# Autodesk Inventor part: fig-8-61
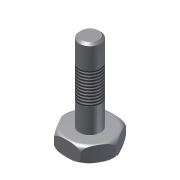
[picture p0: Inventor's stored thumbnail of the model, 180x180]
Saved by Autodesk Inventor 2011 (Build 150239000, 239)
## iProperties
Shininess: 77.0
Length Units: 11269
Angle Units: 11279
Time Units: 11290
Mass Units: 11283
Length Display Precision: 3
Angle Display Precision: 2
Created: 2002-01
Part Number: fig-8-61
Document SubType Name: Modeling
Designer: ***
Density: 1 g/cm^3
Density: 0.0
Volumn: 0.0
Area: 0.0
PropertySet Name: Model Information
Control State: 0
Master: False
Checked Out: False
Author: ***
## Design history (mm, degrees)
sketch "Sketch1"
  geometry: C1 r 25 at (0, 0)
  constraints: 1 centre point
  dimensions: "d0" = 50 diameter of C1
extrude "Extrusion1" new body sketch "Sketch1" distance "d1" = 15; taper "d2" = 0 deg
fillet "Fillet1" dims "d3" = 5
sketch "Sketch2"
  geometry: L1 (25.058, 0)-(12.529, -21.701); L2 (12.529, -21.701)-(-12.529, -21.701); L3 (-12.529, -21.701)-(-25.058, 0); L4 (-25.058, 0)-(-12.529, 21.701); L5 (-12.529, 21.701)-(12.529, 21.701); L6 (12.529, 21.701)-(25.058, 0); 1 further point
  constraints: 12 end point, 11 other
extrude "Extrusion2" sketch "Sketch2" stored distance "d4" = 15; taper "d5" = 0 deg
sketch "Sketch3"
  geometry: C1 r 10.044 at (0, 0); 1 further point
  constraints: 1 centre point, 1 coincident
extrude "Extrusion3" join sketch "Sketch3" distance "d6" = 75; taper "d7" = 0 deg
chamfer "Chamfer1" distance "d8" = 2; stored, may be unused: second distance "d9" = 2, angle "d16" = 45 deg
thread "Thread3" dims "d14" = 30, "d15" = 20
body "Solid1"
